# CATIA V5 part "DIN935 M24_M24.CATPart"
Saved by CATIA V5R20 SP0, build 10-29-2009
Part number: DIN935 M24_M24
Revision: ANY
Definition: UNKNOWN
Nomenclature: DIN935 M24_M24
Source: Unknown
Bounding box of the stored display mesh (mm): x -18 to 18, y -20.785 to 20.785, z 0 to 27
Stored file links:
  C:\Users\Utente\Desktop\IO LAVORO\3D X SITO CF\X 3D SITO CF 27-09-2020\740T\740T-24\DIN935 M24_M24.CATPart
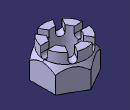
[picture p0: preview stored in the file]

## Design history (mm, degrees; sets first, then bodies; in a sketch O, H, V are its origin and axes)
Body1 "NONE" (main body)
  Solid1: solid without history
